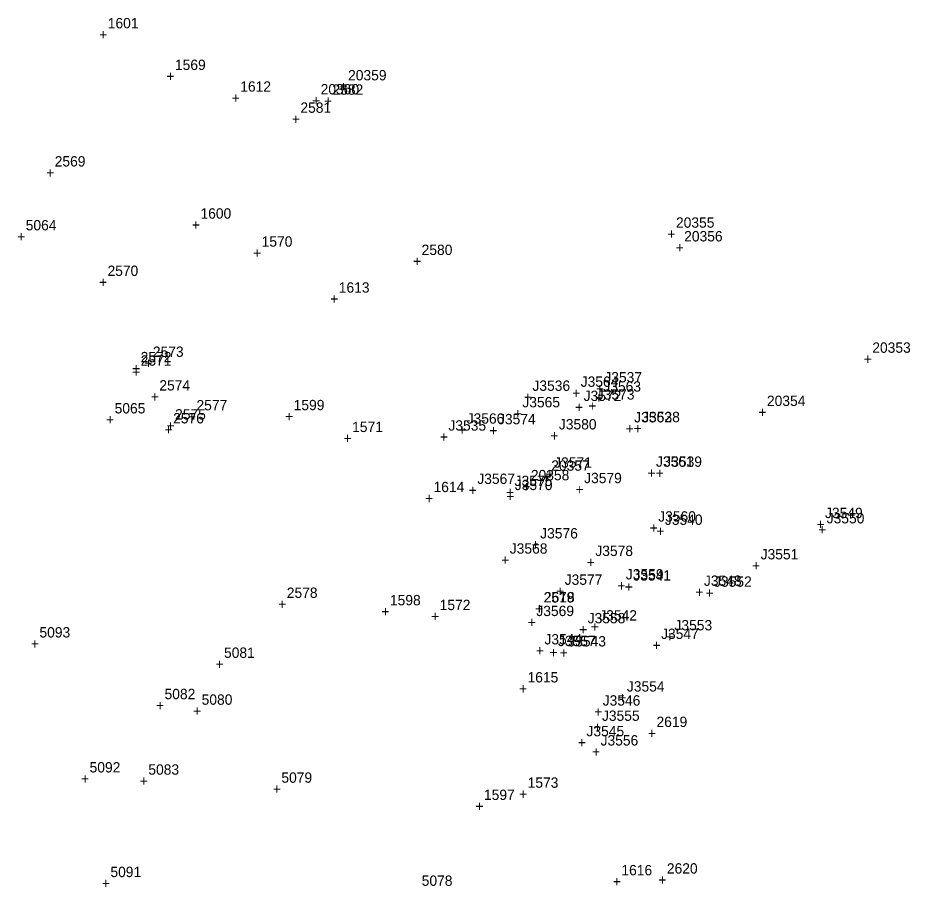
# Model space of a CAD drawing. Extents: x 1036751 to 1042192, y 772604 to 785439.
# Drawn here: x 1039022 to 1039237.7, y 777397.2 to 777607.3 of the extents above; entities that cross this region are included whole.
import ezdxf

# ---------------------------------------------------------------- set-up
doc = ezdxf.new("R2010")
doc.units = 0
for name, color, linetype in [('S_Buildings', 7, 'Continuous'), ('S_Buildings_SillElevation', 7, 'Continuous'), ('S_Ground_Elevation', 7, 'Continuous'), ('S_Property_IronPipeFound', 7, 'Continuous'), ('S_Property_Mailbox', 7, 'Continuous'), ('S_Property_RockBoulder', 7, 'Continuous'), ('S_Roadway_Centerline', 7, 'Continuous'), ('S_Roadway_Drive_Gravel', 7, 'Continuous'), ('S_Roadway_Edge_Pavement', 7, 'Continuous'), ('S_Traffic_Sign_DoublePost', 7, 'Continuous'), ('S_Trees_Conifer_Pay', 7, 'Continuous'), ('S_Utilities_GuyWire3', 7, 'Continuous'), ('S_Utilities_Pole_Power', 7, 'Continuous'), ('S_Utilities_UG_Electrical_Line', 7, 'Continuous')]:
    doc.layers.add(name, color=color, linetype=linetype)

msp = doc.modelspace()

# ---------------------------------------------------------------- texts
at = {"layer": 'S_Buildings'}
for s, p in [('20355', (1039181.09, 777556.55)), ('+', (1039179.02, 777553.8)), ('20353', (1039228.54, 777526.32)), ('+', (1039226.48, 777523.57)), ('20354', (1039203.08, 777513.46)), ('+', (1039201.02, 777510.71))]:
    msp.add_text(s, height=2.5, dxfattribs=at).set_placement(p)
at = {"layer": 'S_Buildings_SillElevation'}
for s, p in [('20356', (1039183.07, 777553.24)), ('+', (1039181.01, 777550.49))]:
    msp.add_text(s, height=2.5, dxfattribs=at).set_placement(p)
at = {"layer": 'S_Ground_Elevation'}
for s, p in [('5064', (1039023.93, 777555.91)), ('+', (1039021.87, 777553.16)), ('J3564', (1039158.06, 777518.09)), ('J3563', (1039163.54, 777516.93)), ('+', (1039156, 777515.34)), ('+', (1039161.48, 777514.18)), ('5065', (1039045.42, 777511.66)), ('J3565', (1039143.96, 777513.13)), ('+', (1039141.9, 777510.38)), ('J3562', (1039170.99, 777509.49)), ('+', (1039043.36, 777508.91)), ('J3566', (1039130.5, 777509.19)), ('J3574', (1039138.07, 777509.04)), ('J3580', (1039152.79, 777507.79)), ('+', (1039128.44, 777506.44)), ('+', (1039136, 777506.29)), ('+', (1039168.93, 777506.74)), ('+', (1039150.73, 777505.04)), ('J3561', (1039176.26, 777498.77)), ('J3567', (1039133.07, 777494.62)), ('J3579', (1039158.9, 777494.8)), ('+', (1039174.2, 777496.02)), ('J3575', (1039142.09, 777494.11)), ('+', (1039131.01, 777491.87)), ('+', (1039140.03, 777491.36)), ('+', (1039156.84, 777492.05)), ('J3560', (1039176.8, 777485.51)), ('J3550', (1039217.52, 777485.08)), ('J3576', (1039148.27, 777481.44)), ('+', (1039174.74, 777482.76)), ('+', (1039215.46, 777482.33)), ('J3568', (1039140.92, 777477.76)), ('+', (1039146.2, 777478.69)), ('J3578', (1039161.6, 777477.2)), ('J3551', (1039201.55, 777476.38)), ('+', (1039138.86, 777475.01)), ('+', (1039159.53, 777474.45)), ('+', (1039199.49, 777473.63)), ('J3559', (1039168.98, 777471.53)), ('J3577', (1039154.19, 777470.23)), ('J3552', (1039190.29, 777469.76)), ('+', (1039152.13, 777467.48)), ('+', (1039166.92, 777468.78)), ('+', (1039188.23, 777467.01)), ('J3569', (1039147.34, 777462.68)), ('J3558', (1039159.75, 777460.93)), ('+', (1039145.28, 777459.93)), ('+', (1039157.69, 777458.18)), ('J3553', (1039180.73, 777459.22)), ('+', (1039178.67, 777456.47)), ('J3557', (1039152.58, 777455.41)), ('+', (1039150.52, 777452.66)), ('J3554', (1039169.22, 777444.43)), ('5080', (1039066.45, 777441.24)), ('+', (1039167.16, 777441.68)), ('+', (1039064.39, 777438.49)), ('J3555', (1039163.2, 777437.35)), ('+', (1039161.14, 777434.6)), ('J3556', (1039162.87, 777431.39)), ('+', (1039160.81, 777428.64)), ('5079', (1039085.72, 777422.39)), ('+', (1039083.66, 777419.64)), ('5078', (1039119.64, 777397.47))]:
    msp.add_text(s, height=2.5, dxfattribs=at).set_placement(p)
at = {"layer": 'S_Property_IronPipeFound'}
for s, p in [('2580', (1039119.62, 777549.96)), ('+', (1039117.56, 777547.21)), ('2578', (1039087.03, 777467.07)), ('+', (1039084.97, 777464.32)), ('2619', (1039176.38, 777435.86)), ('+', (1039174.32, 777433.11))]:
    msp.add_text(s, height=2.5, dxfattribs=at).set_placement(p)
at = {"layer": 'S_Property_Mailbox'}
for s, p in [('2620', (1039178.89, 777400.43)), ('+', (1039176.83, 777397.68))]:
    msp.add_text(s, height=2.5, dxfattribs=at).set_placement(p)
at = {"layer": 'S_Property_RockBoulder'}
for s, p in [('J3572', (1039158.77, 777514.67)), ('J3573', (1039161.96, 777515)), ('+', (1039159.9, 777512.25)), ('+', (1039156.71, 777511.92)), ('J3571', (1039151.65, 777498.54)), ('+', (1039149.59, 777495.79)), ('J3570', (1039142.14, 777493.13)), ('+', (1039140.08, 777490.38))]:
    msp.add_text(s, height=2.5, dxfattribs=at).set_placement(p)
at = {"layer": 'S_Roadway_Centerline'}
for s, p in [('1569', (1039060, 777594.68)), ('+', (1039057.93, 777591.93)), ('1570', (1039080.95, 777551.97)), ('+', (1039078.89, 777549.22)), ('1571', (1039102.82, 777507.16)), ('+', (1039100.76, 777504.41)), ('1572', (1039123.98, 777464.12)), ('+', (1039121.91, 777461.37)), ('1573', (1039145.24, 777421.17)), ('+', (1039143.18, 777418.42))]:
    msp.add_text(s, height=2.5, dxfattribs=at).set_placement(p)
at = {"layer": 'S_Roadway_Drive_Gravel'}
for s, p in [('J3537', (1039163.78, 777519.16)), ('J3536', (1039146.4, 777517.12)), ('+', (1039161.72, 777516.41)), ('+', (1039144.34, 777514.37)), ('J3538', (1039172.92, 777509.55)), ('J3535', (1039126.1, 777507.5)), ('+', (1039170.86, 777506.8)), ('+', (1039124.04, 777504.75)), ('J3539', (1039178.26, 777498.76)), ('+', (1039176.2, 777496.01)), ('J3549', (1039217.12, 777486.36)), ('J3540', (1039178.41, 777484.72)), ('+', (1039176.35, 777481.97)), ('+', (1039215.06, 777483.61)), ('J3541', (1039170.78, 777471.25)), ('J3548', (1039187.84, 777469.98)), ('+', (1039168.72, 777468.5)), ('+', (1039185.78, 777467.23)), ('J3542', (1039162.56, 777461.6)), ('+', (1039160.5, 777458.85)), ('5093', (1039027.25, 777457.5)), ('J3544', (1039149.3, 777455.82)), ('J3547', (1039177.49, 777457.15)), ('+', (1039025.19, 777454.75)), ('J3543', (1039155.06, 777455.33)), ('+', (1039175.43, 777454.4)), ('5081', (1039071.86, 777452.58)), ('+', (1039147.24, 777453.07)), ('+', (1039153, 777452.58)), ('+', (1039069.8, 777449.83)), ('5082', (1039057.49, 777442.59)), ('J3546', (1039163.38, 777441.04)), ('+', (1039055.43, 777439.84)), ('+', (1039161.32, 777438.29)), ('J3545', (1039159.46, 777433.62)), ('+', (1039157.4, 777430.87)), ('5092', (1039039.37, 777424.87)), ('5083', (1039053.57, 777424.33)), ('+', (1039037.31, 777422.12)), ('+', (1039051.51, 777421.58)), ('5091', (1039044.4, 777399.58)), ('+', (1039042.34, 777396.83))]:
    msp.add_text(s, height=2.5, dxfattribs=at).set_placement(p)
at = {"layer": 'S_Roadway_Edge_Pavement'}
for s, p in [('1601', (1039043.76, 777604.75)), ('+', (1039041.7, 777602)), ('1612', (1039075.79, 777589.44)), ('+', (1039073.73, 777586.69)), ('1600', (1039066.17, 777558.75)), ('+', (1039064.11, 777556)), ('1613', (1039099.59, 777540.86)), ('+', (1039097.53, 777538.11)), ('1599', (1039088.69, 777512.44)), ('+', (1039086.63, 777509.69)), ('1614', (1039122.49, 777492.64)), ('+', (1039120.43, 777489.89)), ('1598', (1039111.96, 777465.28)), ('+', (1039109.9, 777462.53)), ('1615', (1039145.21, 777446.63)), ('+', (1039143.15, 777443.88)), ('1597', (1039134.69, 777418.23)), ('+', (1039132.63, 777415.48)), ('1616', (1039167.9, 777400.01)), ('+', (1039165.84, 777397.27))]:
    msp.add_text(s, height=2.5, dxfattribs=at).set_placement(p)
at = {"layer": 'S_Traffic_Sign_DoublePost'}
for s, p in [('20359', (1039101.84, 777592.17)), ('20360', (1039095.21, 777588.78)), ('+', (1039099.77, 777589.42)), ('+', (1039093.15, 777586.03)), ('2577', (1039065.2, 777512.4)), ('2576', (1039059.56, 777509.25)), ('+', (1039063.14, 777509.65)), ('+', (1039057.5, 777506.5)), ('20357', (1039150.95, 777497.81)), ('20358', (1039146.02, 777495.5)), ('+', (1039148.89, 777495.06)), ('+', (1039143.96, 777492.75))]:
    msp.add_text(s, height=2.5, dxfattribs=at).set_placement(p)
at = {"layer": 'S_Trees_Conifer_Pay'}
for s, p in [('2569', (1039030.94, 777571.35)), ('+', (1039028.88, 777568.6)), ('2570', (1039043.7, 777544.9)), ('+', (1039041.64, 777542.15)), ('2571', (1039051.72, 777523.2)), ('+', (1039049.65, 777520.45))]:
    msp.add_text(s, height=2.5, dxfattribs=at).set_placement(p)
at = {"layer": 'S_Utilities_GuyWire3'}
for s, p in [('2582', (1039098.08, 777588.7)), ('+', (1039096.02, 777585.95))]:
    msp.add_text(s, height=2.5, dxfattribs=at).set_placement(p)
at = {"layer": 'S_Utilities_Pole_Power'}
for s, p in [('2581', (1039090.32, 777584.33)), ('+', (1039088.26, 777581.58)), ('2579', (1039149.09, 777465.96)), ('2618', (1039149.18, 777466)), ('+', (1039147.03, 777463.21)), ('+', (1039147.12, 777463.25))]:
    msp.add_text(s, height=2.5, dxfattribs=at).set_placement(p)
at = {"layer": 'S_Utilities_UG_Electrical_Line'}
for s, p in [('2573', (1039054.66, 777525.33)), ('2572', (1039051.71, 777524.03)), ('+', (1039049.65, 777521.28)), ('+', (1039052.6, 777522.58)), ('2574', (1039056.23, 777517.2)), ('+', (1039054.17, 777514.45)), ('2575', (1039060.03, 777510.19)), ('+', (1039057.97, 777507.45))]:
    msp.add_text(s, height=2.5, dxfattribs=at).set_placement(p)

doc.saveas('drawing.dxf')
